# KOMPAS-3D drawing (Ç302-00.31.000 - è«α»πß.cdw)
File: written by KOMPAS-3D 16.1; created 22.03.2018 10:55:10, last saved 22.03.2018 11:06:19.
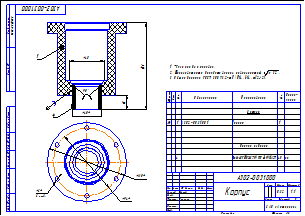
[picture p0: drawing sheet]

Sheet 1: A3, landscape

Title block, sheet 1: name: Корпус; designation: А302-00.31.000; mass: 0,32; scale: 1:1; sheets: 1; organisation: ЗАО «Астерион»; sheet format: A3; stored path: Z:\Мембранные насосы\Мембранный электропривод\А302-00.00.000 - ASTRA-302 (МЭ200)\Чертежи\А302-00.31.000 - Корпус.cdw; drawn by: Милов; technical control: Лучихин

Views: Вид 1, Местный разрез 1, Спереди, Проекционный вид 2
Referenced files in Z:\1 ПКИ 3D\Полипропиленовые фитинги, трубы\: Труба ф40х3,7 (PN10) FV PPR ф. FV PLAST.m3d
Referenced files in Z:\Мембранные насосы\Мембранный электропривод\А302-00.00.000 - ASTRA-302 (МЭ200)\3Д\: А302-00.31.001 - Корпус.m3d, А302-00.31.000 - Корпус.a3d
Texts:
  *Размеры для справок.
  Шероховатость дорабатываемых поверхностей  Ra 3,2 .
  Общие допуски ГОСТ 30893.2-mK (H14, h14,  t2/2).
  Труба ф40х3,7 (PN10) FV PPR ф. FV PLAST
Dimensions and other numbers on the sheet: 20; 120; 40; 48; 1; 4; 94; 110; 6; 6 отв.; 1:1; 0,32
